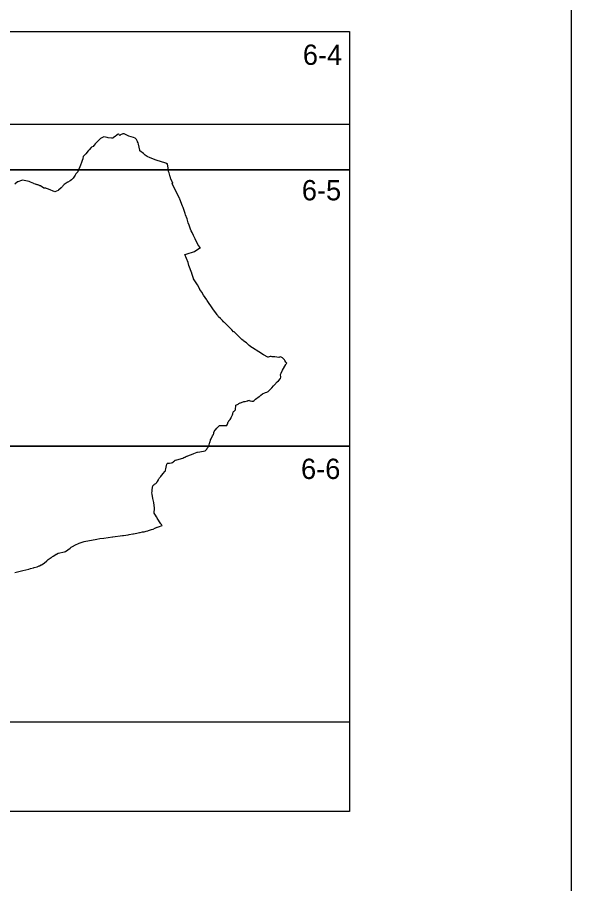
# Model space of a CAD drawing. Extents: x -447352 to -425530, y -1135906 to -1121091.
# Drawn here: x -431506.7 to -431256.1, y -1126663.9 to -1126271.9 of the extents above; entities that cross this region are included whole.
import ezdxf

# ---------------------------------------------------------------- set-up
doc = ezdxf.new("R2010")
doc.units = 0
for name, color, linetype in [('Vrstva 1', 7, 'Continuous'), ('Vrstva 10', 7, 'Continuous'), ('Vrstva 4', 7, 'Continuous')]:
    doc.layers.add(name, color=color, linetype=linetype)

msp = doc.modelspace()

# ---------------------------------------------------------------- linework, layer by layer
at = {"layer": 'Vrstva 1'}
msp.add_lwpolyline([(-432741.1, -1126016.81), (-432741.1, -1127066.81), (-431256.1, -1127066.81), (-431256.1, -1126016.81)], close=True, dxfattribs=at)
msp.add_lwpolyline([(-431507.81, -1126523.09), (-431504.27, -1126522.22), (-431501.5, -1126521.55), (-431500.83, -1126521.34), (-431499.34, -1126520.98), (-431499.13, -1126520.92), (-431497.7, -1126520.53), (-431497.1, -1126520.27), (-431496.88, -1126520.17), (-431496.72, -1126520.11), (-431495.9, -1126519.66), (-431495.84, -1126519.62), (-431494.53, -1126518.84), (-431493.38, -1126517.79), (-431492.73, -1126517.29), (-431492.6, -1126517.18), (-431492.58, -1126517.17), (-431492.42, -1126517.04), (-431492.27, -1126516.94), (-431491.47, -1126516.38), (-431491.41, -1126516.34), (-431491.34, -1126516.29), (-431490.83, -1126515.94), (-431490.46, -1126515.68), (-431489.8, -1126515.22), (-431489.21, -1126514.81), (-431489.05, -1126514.84), (-431489.04, -1126514.84), (-431489.02, -1126514.82), (-431488.29, -1126514.43), (-431485.33, -1126513.85), (-431484.91, -1126513.7), (-431482.88, -1126512.07), (-431482.41, -1126511.73), (-431482.38, -1126511.71), (-431482.02, -1126511.45), (-431481.84, -1126511.33), (-431480.45, -1126510.63), (-431479.04, -1126509.99), (-431478.74, -1126509.84), (-431477.48, -1126509.38), (-431476.48, -1126509.13), (-431470.77, -1126508.07), (-431469.35, -1126507.81), (-431467.64, -1126507.56), (-431463.77, -1126506.99), (-431463.53, -1126506.96), (-431459.23, -1126506.44), (-431458.7, -1126506.38), (-431456.55, -1126506.02), (-431456.23, -1126505.97), (-431454.57, -1126505.7), (-431454.17, -1126505.63), (-431452.76, -1126505.34), (-431451.47, -1126505.07), (-431451.26, -1126505.03), (-431450.09, -1126504.8), (-431449.42, -1126504.67), (-431449.4, -1126504.67), (-431448.49, -1126504.46), (-431448.42, -1126504.44), (-431447.77, -1126504.28), (-431447.42, -1126504.17), (-431446.53, -1126503.88), (-431446.09, -1126503.73), (-431445.44, -1126503.49), (-431445.32, -1126503.45), (-431444.23, -1126502.96), (-431444.23, -1126502.96), (-431444.11, -1126502.92), (-431443.46, -1126502.69), (-431443.37, -1126502.66), (-431442.94, -1126502.5), (-431441.28, -1126501.92), (-431441.3, -1126501.87), (-431441.41, -1126501.7), (-431441.57, -1126501.47), (-431441.79, -1126501.15), (-431443.49, -1126498.51), (-431443.7, -1126498.16), (-431443.87, -1126497.89), (-431444.31, -1126497.18), (-431444.84, -1126496.33), (-431444.68, -1126493.97), (-431444.67, -1126493.88), (-431445.06, -1126491.58), (-431445.06, -1126491.56), (-431445.07, -1126491.54), (-431445.07, -1126491.54), (-431445.07, -1126491.51), (-431445.48, -1126489.68), (-431445.49, -1126489.49), (-431445.55, -1126488.69), (-431445.65, -1126488.41), (-431445.66, -1126488.39), (-431445.77, -1126488.17), (-431445.81, -1126488.09), (-431445.82, -1126487.71), (-431445.85, -1126487.01), (-431445.8, -1126486.52), (-431445.8, -1126486.5), (-431445.71, -1126485.64), (-431445.69, -1126485.53), (-431445.4, -1126483.89), (-431445.32, -1126483.81), (-431445.02, -1126483.47), (-431444.96, -1126483.4), (-431444.7, -1126483.28), (-431444.64, -1126483.22), (-431444.38, -1126483.02), (-431444.15, -1126482.84), (-431443.94, -1126482.68), (-431443.88, -1126482.64), (-431443.8, -1126482.51), (-431443.72, -1126482.39), (-431443.61, -1126482.22), (-431443.39, -1126481.89), (-431442.97, -1126481.24), (-431442.84, -1126480.99), (-431442.83, -1126480.98), (-431442.69, -1126480.69), (-431442.64, -1126480.6), (-431442.46, -1126480.27), (-431442.32, -1126480.12), (-431442.02, -1126479.81), (-431441.85, -1126479.63), (-431441.57, -1126479.28), (-431441.44, -1126479.11), (-431440.75, -1126478.26), (-431440.09, -1126477.45), (-431439.8, -1126477.09), (-431439.56, -1126475.92), (-431439.5, -1126475.69), (-431439.43, -1126475.41), (-431439.11, -1126474.1), (-431439.03, -1126473.82), (-431439.03, -1126473.79), (-431439.01, -1126473.74), (-431438.85, -1126473.73), (-431438.83, -1126473.73), (-431438.59, -1126473.73), (-431437.9, -1126473.71), (-431437.89, -1126473.71), (-431437.86, -1126473.71), (-431437.18, -1126473.53), (-431436.98, -1126473.47), (-431436.56, -1126473.36), (-431436.54, -1126473.35), (-431436.48, -1126473.29), (-431436.18, -1126473.01), (-431436.06, -1126472.93), (-431435.72, -1126472.67), (-431435.3, -1126472.35), (-431435.23, -1126472.33), (-431434.67, -1126472.17), (-431431.97, -1126471.41), (-431431.38, -1126471.14), (-431431.05, -1126470.98), (-431431, -1126470.96), (-431430.9, -1126470.91), (-431430.54, -1126470.73), (-431430.49, -1126470.71), (-431430.46, -1126470.69), (-431430.45, -1126470.69), (-431430.42, -1126470.67), (-431430.11, -1126470.52), (-431430.05, -1126470.48), (-431429.94, -1126470.43), (-431428.86, -1126470.1), (-431428.43, -1126469.92), (-431427.91, -1126469.7), (-431426.9, -1126469.29), (-431425.48, -1126468.66), (-431425.34, -1126468.65), (-431424.21, -1126468.6), (-431421.81, -1126468.04), (-431421.28, -1126467.64), (-431421.21, -1126467.52), (-431421.12, -1126467.34), (-431420.86, -1126466.83), (-431420.51, -1126466.4), (-431420.49, -1126466.37), (-431420.28, -1126466.08), (-431420.17, -1126465.92), (-431420.16, -1126465.91), (-431419.62, -1126464.13), (-431419.61, -1126464.1), (-431419.41, -1126463.15), (-431419.15, -1126462.69), (-431418.96, -1126462.36), (-431418.41, -1126461.24), (-431418.03, -1126460.73), (-431418, -1126460.6), (-431417.93, -1126460.3), (-431417.9, -1126460.16), (-431417.84, -1126459.91), (-431417.82, -1126459.81), (-431417.5, -1126458.8), (-431417.49, -1126458.79), (-431417.2, -1126458.51), (-431416.54, -1126457.88), (-431416.49, -1126457.83), (-431416.02, -1126457.35), (-431415.76, -1126457.09), (-431415.66, -1126456.98), (-431415.29, -1126456.66), (-431415.25, -1126456.66), (-431415.24, -1126456.66), (-431414.83, -1126456.65), (-431414.66, -1126456.66), (-431414.03, -1126456.68), (-431413.32, -1126456.68), (-431412.35, -1126456.59), (-431412.32, -1126456.59), (-431412.07, -1126456.56), (-431411.85, -1126456.2), (-431411.8, -1126456.07), (-431411.78, -1126456.02), (-431411.76, -1126455.96), (-431411.4, -1126454.94), (-431411.26, -1126454.77), (-431411.16, -1126454.66), (-431411.12, -1126454.62), (-431411.06, -1126454.54), (-431410.94, -1126454.41), (-431410.67, -1126454.09), (-431410.58, -1126453.99), (-431410.48, -1126453.87), (-431410.14, -1126453.48), (-431410.07, -1126453.09), (-431410.01, -1126452.78), (-431409.94, -1126452.65), (-431409.39, -1126451.73), (-431409.28, -1126451.34), (-431409.09, -1126450.64), (-431408.97, -1126450.35), (-431408.68, -1126450.08), (-431408.13, -1126449.57), (-431408.06, -1126449.51), (-431407.96, -1126447.4), (-431406.94, -1126446.91), (-431406.54, -1126446.7), (-431406.29, -1126446.57), (-431406, -1126446.41), (-431405.78, -1126446.33), (-431405.44, -1126446.2), (-431405.39, -1126446.19), (-431404.3, -1126445.78), (-431404.29, -1126445.78), (-431403.8, -1126445.72), (-431403.72, -1126445.7), (-431402.69, -1126445.44), (-431402.54, -1126445.4), (-431402.45, -1126445.37), (-431402.28, -1126445.32), (-431401.75, -1126445.15), (-431401.75, -1126445.15), (-431401.74, -1126445.16), (-431401.74, -1126445.16), (-431401.71, -1126445.22), (-431401.58, -1126445.44), (-431400.7, -1126445.54), (-431400.5, -1126445.56), (-431400.14, -1126445.6), (-431400.05, -1126445.56), (-431399.62, -1126445.38), (-431398.97, -1126444.67), (-431397.33, -1126443.51), (-431397.24, -1126443.44), (-431397.07, -1126443.33), (-431396.56, -1126442.91), (-431395.81, -1126442.31), (-431394.54, -1126441.74), (-431393.92, -1126441.47), (-431393.38, -1126441.23), (-431393.32, -1126441.2), (-431391.67, -1126439.53), (-431390.83, -1126438.64), (-431390.47, -1126438.26), (-431389.28, -1126436.9), (-431388.68, -1126436.44), (-431388.63, -1126436.4), (-431387.79, -1126435.39), (-431387.59, -1126434.82), (-431387.68, -1126433.49), (-431387.46, -1126433), (-431386.82, -1126431.55), (-431385.36, -1126429.07), (-431385.33, -1126429.02), (-431385.33, -1126429.02), (-431385.31, -1126428.99), (-431385.28, -1126428.95), (-431385.13, -1126428.76), (-431384.87, -1126428.42), (-431385.13, -1126428.12), (-431385.27, -1126427.9), (-431385.74, -1126427.16), (-431385.94, -1126426.97), (-431386.09, -1126426.81), (-431386.28, -1126426.61), (-431386.86, -1126426.04), (-431387.71, -1126425.57), (-431388.16, -1126425.75), (-431388.49, -1126425.87), (-431390.24, -1126425.6), (-431390.85, -1126425.51), (-431390.99, -1126425.5), (-431391.58, -1126425.48), (-431391.96, -1126425.43), (-431392.12, -1126425.4), (-431392.16, -1126425.4), (-431392.19, -1126425.39), (-431392.19, -1126425.39), (-431392.22, -1126425.4), (-431392.32, -1126425.43), (-431392.45, -1126425.46), (-431393.35, -1126425.7), (-431393.42, -1126425.67), (-431395.49, -1126424.63), (-431397.51, -1126423.35), (-431400.42, -1126421.53), (-431400.58, -1126421.39), (-431400.62, -1126421.36), (-431400.71, -1126421.28), (-431401.85, -1126420.35), (-431403, -1126419.3), (-431403.11, -1126419.2), (-431404.32, -1126418.44), (-431404.6, -1126418.21), (-431405.23, -1126417.71), (-431405.54, -1126417.47), (-431406.04, -1126416.94), (-431406.76, -1126416.18), (-431406.91, -1126416.02), (-431407.37, -1126415.53), (-431408.34, -1126414.5), (-431408.54, -1126414.39), (-431408.54, -1126414.39), (-431408.72, -1126414.3), (-431408.92, -1126414.2), (-431409.75, -1126413.37), (-431410.38, -1126412.74), (-431411.56, -1126411.57), (-431412.49, -1126410.63), (-431412.65, -1126410.48), (-431413.09, -1126410.03), (-431413.33, -1126409.79), (-431413.42, -1126409.7), (-431413.46, -1126409.66), (-431413.98, -1126409.14), (-431414.62, -1126408.49), (-431414.7, -1126408.41), (-431414.72, -1126408.39), (-431414.87, -1126408.24), (-431415.7, -1126407.4), (-431416.08, -1126406.9), (-431416.36, -1126406.53), (-431416.68, -1126406.1), (-431417.04, -1126405.62), (-431417.99, -1126404.36), (-431418.36, -1126403.82), (-431420.9, -1126400.08), (-431421.07, -1126399.82), (-431421.84, -1126398.63), (-431422.51, -1126397.62), (-431423.35, -1126396.29), (-431424.15, -1126395.02), (-431424.23, -1126394.89), (-431425.32, -1126393.04), (-431427, -1126390.19), (-431427, -1126390.18), (-431427, -1126390.18), (-431427.01, -1126390.18), (-431427.34, -1126389.2), (-431427.79, -1126387.9), (-431427.85, -1126387.7), (-431429.23, -1126384.19), (-431429.52, -1126382.94), (-431431, -1126379.26), (-431430.37, -1126379.06), (-431426.65, -1126377.82), (-431424.68, -1126376.6), (-431424.5, -1126376.49), (-431424.44, -1126376.45), (-431424.24, -1126376.33), (-431423.97, -1126376.16), (-431424.89, -1126374.97), (-431426.3, -1126372.19), (-431427.05, -1126370.72), (-431427.58, -1126369.56), (-431427.6, -1126369.52), (-431427.66, -1126369.39), (-431427.67, -1126369.36), (-431427.69, -1126369.33), (-431427.73, -1126369.24), (-431428.06, -1126368.51), (-431428.38, -1126367.72), (-431429.09, -1126365.95), (-431429.5, -1126364.91), (-431429.65, -1126364.28), (-431429.91, -1126363.15), (-431430.65, -1126361.26), (-431430.85, -1126360.66), (-431431.79, -1126358.03), (-431432.06, -1126357.31), (-431433.25, -1126354.22), (-431433.32, -1126354.04), (-431433.35, -1126353.96), (-431436.7, -1126347.15), (-431436.39, -1126347.01), (-431436.37, -1126347), (-431436.47, -1126346.83), (-431436.55, -1126346.73), (-431436.72, -1126346.5), (-431436.78, -1126346.42), (-431437.39, -1126344.94), (-431437.44, -1126344.65), (-431437.54, -1126344.19), (-431437.55, -1126344.13), (-431438.06, -1126342.29), (-431438.36, -1126341.66), (-431438.37, -1126341.58), (-431438.41, -1126341.22), (-431438.55, -1126340.13), (-431438.83, -1126338.29), (-431438.89, -1126338.27), (-431439.19, -1126338.17), (-431439.57, -1126337.91), (-431439.58, -1126337.91), (-431443.88, -1126336.5), (-431446.67, -1126335.52), (-431447.98, -1126334.9), (-431448.95, -1126334.34), (-431449.67, -1126333.56), (-431451.35, -1126332.29), (-431451.41, -1126331.99), (-431451.99, -1126329.29), (-431452.14, -1126328.75), (-431452.32, -1126328.24), (-431452.37, -1126328.08), (-431452.62, -1126327.56), (-431452.87, -1126327.25), (-431453.45, -1126326.56), (-431454.2, -1126326.35), (-431456.38, -1126325.69), (-431458.47, -1126324.73), (-431459.09, -1126324.73), (-431460.04, -1126325.1), (-431460.17, -1126325.19), (-431460.24, -1126325.24), (-431460.38, -1126325.34), (-431460.42, -1126325.37), (-431460.44, -1126325.35), (-431460.65, -1126325.1), (-431460.9, -1126324.82), (-431460.98, -1126324.72), (-431461.07, -1126324.76), (-431461.58, -1126325.15), (-431461.77, -1126325.3), (-431462.44, -1126325.82), (-431463.19, -1126326.38), (-431463.53, -1126326.6), (-431464.12, -1126326.56), (-431465.6, -1126326.41), (-431466.06, -1126326.32), (-431467.65, -1126326), (-431467.95, -1126326.11), (-431468.51, -1126326.46), (-431469.06, -1126326.78), (-431469.55, -1126327.24), (-431470.08, -1126327.73), (-431470.48, -1126328.12), (-431470.49, -1126328.13), (-431470.82, -1126328.47), (-431470.95, -1126328.61), (-431471.46, -1126329.16), (-431471.91, -1126329.71), (-431472.07, -1126329.9), (-431472.43, -1126330.33), (-431473.17, -1126330.66), (-431473.19, -1126330.66), (-431473.39, -1126330.91), (-431474.25, -1126331.93), (-431474.63, -1126332.38), (-431475.76, -1126333.74), (-431475.77, -1126333.75), (-431477.01, -1126334.92), (-431477.13, -1126335.76), (-431477.18, -1126336.13), (-431477.22, -1126336.23), (-431477.7, -1126337.58), (-431478.14, -1126338.82), (-431478.17, -1126338.9), (-431478.47, -1126339.59), (-431479.4, -1126341.77), (-431479.42, -1126341.78), (-431479.99, -1126342.46), (-431480.29, -1126342.81), (-431480.29, -1126342.82), (-431480.63, -1126343.36), (-431481.5, -1126344.75), (-431481.59, -1126344.89), (-431481.76, -1126345.02), (-431482.29, -1126345.41), (-431482.9, -1126345.86), (-431482.9, -1126345.86), (-431483.87, -1126346.49), (-431484, -1126346.58), (-431484.18, -1126346.7), (-431485.48, -1126347.56), (-431485.49, -1126347.57), (-431485.75, -1126347.83), (-431485.87, -1126347.95), (-431486.09, -1126348.18), (-431486.37, -1126348.46), (-431486.94, -1126349.03), (-431488.1, -1126350.19), (-431488.3, -1126350.27), (-431489.8, -1126350.84), (-431492.61, -1126349.72), (-431492.61, -1126349.73), (-431492.62, -1126349.75), (-431493.53, -1126349.37), (-431493.84, -1126349.24), (-431493.86, -1126349.24), (-431494.25, -1126349.24), (-431494.73, -1126349.24), (-431496.29, -1126348.25), (-431496.55, -1126348.12), (-431496.84, -1126347.96), (-431496.9, -1126347.93), (-431496.94, -1126347.91), (-431497.48, -1126347.68), (-431497.53, -1126347.68), (-431497.54, -1126347.68), (-431497.69, -1126347.67), (-431497.81, -1126347.66), (-431498.12, -1126347.64), (-431498.14, -1126347.64), (-431498.14, -1126347.64), (-431498.25, -1126347.6), (-431498.49, -1126347.5), (-431499.09, -1126347.25), (-431499.25, -1126347.18), (-431500.77, -1126346.45), (-431501.39, -1126346.27), (-431502.06, -1126346.07), (-431504.38, -1126345.64), (-431504.39, -1126345.64), (-431504.79, -1126345.75), (-431506.53, -1126346.33), (-431506.66, -1126346.44), (-431507.87, -1126347.4)], dxfattribs=at)
at = {"layer": 'Vrstva 10'}
msp.add_lwpolyline([(-431356.51, -1126320.23), (-431356.51, -1126631.21), (-431689.38, -1126631.21), (-431689.38, -1126465.91), (-431669.01, -1126465.91), (-431669.01, -1126340.91), (-431669.01, -1126320.23), (-431356.51, -1126320.23)], dxfattribs=at)
at = {"layer": 'Vrstva 4'}
msp.add_line((-431669.01, -1126278.41), (-431356.51, -1126278.41), dxfattribs=at)
msp.add_lwpolyline([(-431356.51, -1126278.41), (-431356.51, -1126340.91), (-431512.76, -1126340.91), (-431512.76, -1126278.41)], dxfattribs=at)
for points in [[(-431356.51, -1126340.91), (-431356.51, -1126465.91), (-431512.76, -1126465.91), (-431512.76, -1126340.91)], [(-431356.51, -1126465.91), (-431356.51, -1126590.91), (-431512.76, -1126590.91), (-431512.76, -1126465.91)]]:
    msp.add_lwpolyline(points, close=True, dxfattribs=at)

# ---------------------------------------------------------------- texts
at = {"layer": 'Vrstva 1'}
for s, p in [('6-4', (-431377.64, -1126293.46)), ('6-5', (-431378.09, -1126354.75)), ('6-6', (-431378.46, -1126480.82))]:
    msp.add_text(s, height=9.2, dxfattribs=at).set_placement(p)

doc.saveas('drawing.dxf')
